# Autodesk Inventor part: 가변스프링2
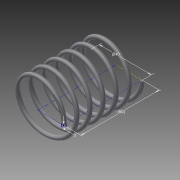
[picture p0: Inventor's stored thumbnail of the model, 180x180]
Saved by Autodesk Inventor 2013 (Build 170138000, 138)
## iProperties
Created: 2018-02
Part Number: 가변스프링2
Material: 일반
Document SubType Name: Modeling
Designer: Administrator
Density: 1 g/cm^3
Author: Administrator
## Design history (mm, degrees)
sketch "스케치1"
  geometry: L1 (0, 0)-(20, 0); L2 (20, 0)-(20, 47.25); L3 (20, 47.25)-(0, 47.25); L4 (0, 47.25)-(0, 0); C1 r 1.5 at (20, 0)
  constraints: 8 end point, 2 parallel, 1 centre point, 1 coincident, 1 horizontal, 1 perpendicular
  dimensions: "d0" = 40 diameter of L2 L4; "d2" = 47.25 distance of L1.end L2.end (derived); "d3" = 3 diameter of C1
feature "코일1" pitch "d4" = 10; turns "d6" = 6; dims "d5" = 47.25 (= d2), "d7" = 0, angle "d8" = 90 deg, angle "d9" = 90 deg, "d10" = 0, "d11" = 0
sketch "스케치2"
  geometry: L1 (-18.5, 0)-(-21.5, 0) reference; 1 further point
  constraints: 1 horizontal alignment
extrude "돌출1" cut sketch "스케치2" stored distance "d12" = 10; taper "d13" = 0 deg
node "작업 평면1"
sketch "스케치3"
  geometry: L1 (-1.5, 0)-(1.5, 0) reference; 1 further point
  constraints: 1 horizontal alignment
extrude "돌출2" cut sketch "스케치3" stored distance "d14" = 10; taper "d15" = 0 deg
node "솔리드1"
node "절단 모서리 투영1"
node "절단 모서리 투영2"
